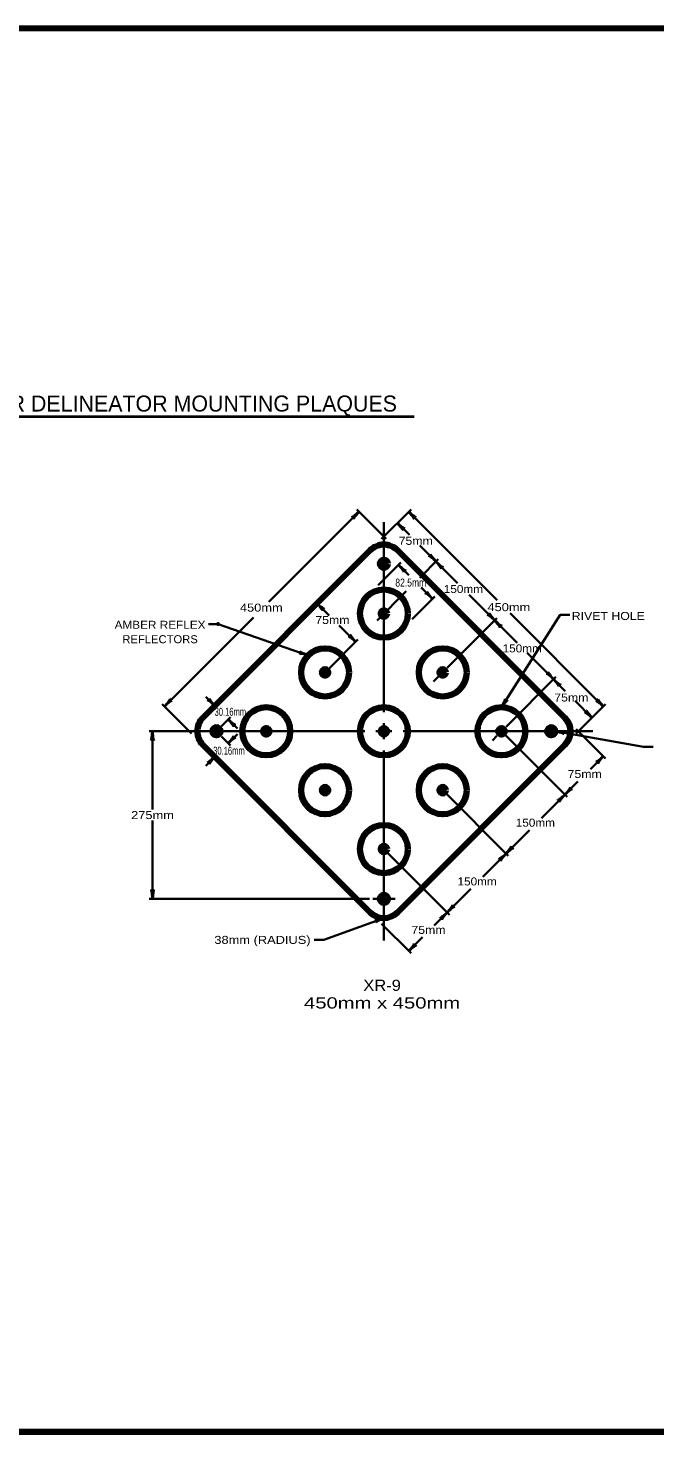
# Model space of a CAD drawing. Extents: x -74 to 639, y -412 to 42.
# Drawn here: x 181.5 to 377.5, y -402.1 to 36.3 of the extents above; entities that cross this region are included whole.
import ezdxf
from ezdxf.enums import TextEntityAlignment as Align

# ---------------------------------------------------------------- set-up
doc = ezdxf.new("R2010")
doc.units = 0
doc.header["$PDMODE"] = 32
doc.header["$PDSIZE"] = 0.5
doc.layers.add('1', color=7, linetype='Continuous', lineweight=40)

msp = doc.modelspace()

# ---------------------------------------------------------------- linework, layer by layer
at = {"layer": '1'}
msp.add_line((95.322, -84.95), (302.217, -84.95), dxfattribs=at)
at = {"layer": '1', "lineweight": 35}
for p, q in [((293.419, -123.164), (284.227, -113.972)), ((292.005, -123.164), (301.197, -113.972)), ((284.934, -114.679), (256.768, -142.845)), ((292.712, -117.942), (292.712, -177.268)), ((300.685, -121.945), (296.955, -118.215)), ((300.49, -114.679), (328.115, -142.303)), ((308.976, -130.235), (303.969, -125.228)), ((290.944, -137.66), (298.015, -130.589)), ((297.308, -131.296), (300.49, -134.478)), ((303.903, -135.308), (309.683, -129.528)), ((308.976, -130.235), (315.739, -136.999)), ((290.591, -148.62), (299.696, -139.515)), ((304.387, -138.374), (307.915, -141.902)), ((275.617, -147.082), (271.853, -143.317)), ((301.551, -148.266), (308.622, -141.195)), ((319.427, -140.687), (327.361, -148.62)), ((251.934, -147.679), (224.123, -175.49)), ((328.068, -147.913), (312.511, -163.469)), ((327.361, -148.62), (334.38, -155.64)), ((332.207, -146.395), (361.302, -175.49)), ((240.885, -149.766), (237.885, -149.766)), ((269.024, -159.58), (240.885, -149.766)), ((283.873, -155.338), (278.717, -150.182)), ((274.327, -164.884), (284.58, -154.63)), ((337.512, -158.772), (345.745, -167.005)), ((309.683, -166.297), (308.269, -167.711)), ((311.804, -164.177), (310.39, -165.591)), ((330.896, -181.854), (346.452, -166.298)), ((345.745, -167.005), (349.434, -170.694)), ((232.608, -183.975), (223.416, -174.783)), ((239.856, -175.313), (237.027, -172.485)), ((352.465, -173.725), (357.766, -179.026)), ((352.816, -183.975), (362.009, -174.783)), ((241.977, -181.677), (244.806, -178.849)), ((244.099, -179.556), (246.927, -182.384)), ((219.386, -183.268), (286.712, -183.268)), ((220.386, -183.268), (220.386, -207.719)), ((290.212, -183.268), (295.212, -183.268)), ((292.712, -180.768), (292.712, -185.768)), ((298.712, -183.268), (358.038, -183.268)), ((328.775, -183.975), (330.189, -182.561)), ((329.482, -183.268), (349.988, -203.774)), ((352.816, -182.561), (362.009, -191.754)), ((241.977, -184.859), (244.806, -187.688)), ((244.099, -186.981), (246.927, -184.152)), ((328.067, -184.683), (326.653, -186.097)), ((239.856, -191.223), (237.028, -194.052)), ((292.712, -189.268), (292.712, -248.594)), ((361.302, -191.046), (357.301, -195.047)), ((311.097, -201.653), (331.603, -222.159)), ((220.386, -211.168), (220.386, -235.594)), ((313.218, -240.544), (292.712, -220.038)), ((288.212, -235.594), (219.386, -235.594)), ((292.712, -235.594), (289.212, -235.594)), ((292.712, -235.594), (296.212, -235.594)), ((292.005, -243.372), (301.197, -252.565)), ((304.83, -247.517), (300.49, -251.858))]:
    msp.add_line(p, q, dxfattribs=at)
at = {"layer": '1', "lineweight": 90}
for p, q in [((236.144, -179.026), (288.47, -126.7)), ((296.955, -126.7), (349.281, -179.026)), ((288.47, -239.837), (236.144, -187.511)), ((349.281, -187.511), (296.955, -239.837))]:
    msp.add_line(p, q, dxfattribs=at)
at = {"layer": '1', "lineweight": 158}
msp.add_line((633.015, -402.068), (-26.651, -402.068), dxfattribs=at)
msp.add_lwpolyline([(633.015, 36.349), (-26.735, 36.265), (-26.651, -402.068)], dxfattribs=at)
at = {"layer": '1', "lineweight": 35}
for points in [[(329.482, -175.768), (347.822, -146.943), (350.822, -146.943)], [(346.288, -183.268), (373.863, -188.13), (376.863, -188.13)], [(353.363, -198.985), (349.281, -203.067), (341.942, -210.406)], [(338.202, -214.147), (330.896, -221.452), (323.626, -228.722)], [(319.928, -232.42), (312.511, -239.837), (308.463, -243.885)], [(292.712, -241.594), (273.918, -248.435), (270.918, -248.435)]]:
    msp.add_lwpolyline(points, dxfattribs=at)
at = {"layer": '1', "lineweight": 90}
for centre, radius in [((292.712, -130.942), 1.25), ((292.712, -146.499), 7.5), ((292.712, -146.499), 1), ((274.327, -164.884), 7.5), ((311.097, -164.884), 7.5), ((274.327, -164.884), 1), ((311.097, -164.884), 1), ((255.943, -183.268), 7.5), ((292.712, -183.268), 7.5), ((329.482, -183.268), 7.5), ((240.386, -183.268), 1.25), ((255.943, -183.268), 1), ((292.712, -183.268), 1), ((329.482, -183.268), 1), ((345.038, -183.268), 1.25), ((274.327, -201.653), 7.5), ((311.097, -201.653), 7.5), ((274.327, -201.653), 1), ((311.097, -201.653), 1), ((292.712, -220.038), 7.5), ((292.712, -220.038), 1), ((292.712, -235.594), 1.25)]:
    msp.add_circle(centre, radius, dxfattribs=at)
for centre, start, end in [((292.712, -130.942), 45, 135.00014), ((240.386, -183.268), 134.99979, 225), ((345.038, -183.268), 315.00029, 45), ((292.712, -235.594), 225, 314.99989)]:
    msp.add_arc(centre, 6, start, end, dxfattribs=at)
at = {"layer": '1'}
for centre, major_axis, ratio, start_param, end_param in [((283.992, -115.322), (1.366, 1.118), 0.07063, 3.1407148, 5.41811), ((283.992, -115.322), (1.366, 1.118), 0.07063, 3.1407148, 5.41811), ((284.358, -115.646), (1.152, 1.373), 0.122415, 0.8963533, 3.1415927), ((284.358, -115.646), (1.152, 1.373), 0.122415, 0.8963533, 3.1415927), ((297.598, -119.156), (-1.118, 1.366), 0.07063, 3.1407148, 5.41811), ((297.598, -119.156), (-1.118, 1.366), 0.07063, 3.1407148, 5.41811), ((297.922, -118.791), (-1.373, 1.152), 0.122415, 0.8963533, 3.1415927), ((297.922, -118.791), (-1.373, 1.152), 0.122415, 0.8963533, 3.1415927), ((301.133, -115.621), (-1.118, 1.366), 0.07063, 3.1407148, 5.41811), ((301.133, -115.621), (-1.118, 1.366), 0.07063, 3.1407148, 5.41811), ((301.457, -115.255), (-1.373, 1.152), 0.122415, 0.8963533, 3.1415927), ((301.457, -115.255), (-1.373, 1.152), 0.122415, 0.8963533, 3.1415927), ((297.951, -132.238), (-1.118, 1.366), 0.07063, 3.1407148, 5.41811), ((297.951, -132.238), (-1.118, 1.366), 0.07063, 3.1407148, 5.41811), ((298.275, -131.872), (-1.373, 1.152), 0.122415, 0.8963533, 3.1415927), ((298.275, -131.872), (-1.373, 1.152), 0.122415, 0.8963533, 3.1415927), ((308.009, -129.659), (1.373, -1.152), 0.122415, 0.8963533, 3.1415927), ((308.009, -129.659), (1.373, -1.152), 0.122415, 0.8963533, 3.1415927), ((308.333, -129.293), (1.118, -1.366), 0.07063, 3.1407148, 5.41811), ((308.333, -129.293), (1.118, -1.366), 0.07063, 3.1407148, 5.41811), ((309.618, -131.177), (-1.118, 1.366), 0.07063, 3.1407148, 5.41811), ((309.618, -131.177), (-1.118, 1.366), 0.07063, 3.1407148, 5.41811), ((309.943, -130.812), (-1.373, 1.152), 0.122415, 0.8963533, 3.1415927), ((309.943, -130.812), (-1.373, 1.152), 0.122415, 0.8963533, 3.1415927), ((306.948, -141.326), (1.373, -1.152), 0.122415, 0.8963533, 3.1415927), ((306.948, -141.326), (1.373, -1.152), 0.122415, 0.8963533, 3.1415927), ((307.272, -140.96), (1.118, -1.366), 0.07063, 3.1407148, 5.41811), ((307.272, -140.96), (1.118, -1.366), 0.07063, 3.1407148, 5.41811), ((272.495, -144.259), (-1.118, 1.366), 0.07063, 3.1407148, 5.41811), ((272.495, -144.259), (-1.118, 1.366), 0.07063, 3.1407148, 5.41811), ((272.82, -143.893), (-1.373, 1.152), 0.122415, 0.8963533, 3.1415927), ((272.82, -143.893), (-1.373, 1.152), 0.122415, 0.8963533, 3.1415927), ((326.394, -148.044), (1.373, -1.152), 0.122415, 0.8963533, 3.1415927), ((326.394, -148.044), (1.373, -1.152), 0.122415, 0.8963533, 3.1415927), ((326.718, -147.678), (1.118, -1.366), 0.07063, 3.1407148, 5.41811), ((326.718, -147.678), (1.118, -1.366), 0.07063, 3.1407148, 5.41811), ((328.003, -149.562), (-1.118, 1.366), 0.07063, 3.1407148, 5.41811), ((328.003, -149.562), (-1.118, 1.366), 0.07063, 3.1407148, 5.41811), ((328.327, -149.196), (-1.373, 1.152), 0.122415, 0.8963533, 3.1415927), ((328.327, -149.196), (-1.373, 1.152), 0.122415, 0.8963533, 3.1415927), ((283.231, -154.396), (1.118, -1.366), 0.07063, 3.1407148, 5.41811), ((283.231, -154.396), (1.118, -1.366), 0.07063, 3.1407148, 5.41811), ((282.906, -154.761), (1.373, -1.152), 0.122415, 0.8963533, 3.1415927), ((282.906, -154.761), (1.373, -1.152), 0.122415, 0.8963533, 3.1415927), ((267.903, -159.482), (1.738, -0.441), 0.122415, 0.8963533, 3.1415927), ((268.036, -159.011), (1.601, -0.744), 0.07063, 3.1407148, 5.41811), ((344.778, -166.429), (1.373, -1.152), 0.122415, 0.8963533, 3.1415927), ((344.778, -166.429), (1.373, -1.152), 0.122415, 0.8963533, 3.1415927), ((345.103, -166.063), (1.118, -1.366), 0.07063, 3.1407148, 5.41811), ((345.103, -166.063), (1.118, -1.366), 0.07063, 3.1407148, 5.41811), ((346.388, -167.947), (-1.118, 1.366), 0.07063, 3.1407148, 5.41811), ((346.388, -167.947), (-1.118, 1.366), 0.07063, 3.1407148, 5.41811), ((346.712, -167.581), (-1.373, 1.152), 0.122415, 0.8963533, 3.1415927), ((346.712, -167.581), (-1.373, 1.152), 0.122415, 0.8963533, 3.1415927), ((224.699, -174.523), (-1.152, -1.373), 0.122415, 0.8963533, 3.1415927), ((224.699, -174.523), (-1.152, -1.373), 0.122415, 0.8963533, 3.1415927), ((225.065, -174.847), (-1.366, -1.118), 0.07063, 3.1407148, 5.41811), ((225.065, -174.847), (-1.366, -1.118), 0.07063, 3.1407148, 5.41811), ((238.889, -174.737), (1.373, -1.152), 0.122415, 0.8963533, 3.1415927), ((238.889, -174.737), (1.373, -1.152), 0.122415, 0.8963533, 3.1415927), ((239.213, -174.371), (1.118, -1.366), 0.07063, 3.1407148, 5.41811), ((239.213, -174.371), (1.118, -1.366), 0.07063, 3.1407148, 5.41811), ((329.834, -174.699), (-0.827, -1.59), 0.122415, 0.8963533, 3.1415927), ((329.834, -174.699), (-0.827, -1.59), 0.122415, 0.8963533, 3.1415927), ((330.262, -174.937), (-1.091, -1.388), 0.07063, 3.1407148, 5.41811), ((330.262, -174.937), (-1.091, -1.388), 0.07063, 3.1407148, 5.41811), ((360.335, -174.914), (1.373, -1.152), 0.122415, 0.8963533, 3.1415927), ((360.335, -174.914), (1.373, -1.152), 0.122415, 0.8963533, 3.1415927), ((360.659, -174.548), (1.118, -1.366), 0.07063, 3.1407148, 5.41811), ((360.659, -174.548), (1.118, -1.366), 0.07063, 3.1407148, 5.41811), ((244.741, -180.498), (-1.118, 1.366), 0.07063, 3.1407148, 5.41811), ((244.741, -180.498), (-1.118, 1.366), 0.07063, 3.1407148, 5.41811), ((245.066, -180.132), (-1.373, 1.152), 0.122415, 0.8963533, 3.1415927), ((245.066, -180.132), (-1.373, 1.152), 0.122415, 0.8963533, 3.1415927), ((356.799, -178.45), (1.373, -1.152), 0.122415, 0.8963533, 3.1415927), ((356.799, -178.45), (1.373, -1.152), 0.122415, 0.8963533, 3.1415927), ((357.123, -178.084), (1.118, -1.366), 0.07063, 3.1407148, 5.41811), ((357.123, -178.084), (1.118, -1.366), 0.07063, 3.1407148, 5.41811), ((220.175, -184.389), (0.176, 1.756), 0.07063, 3.1407148, 5.41811), ((220.175, -184.389), (0.176, 1.756), 0.07063, 3.1407148, 5.41811), ((220.663, -184.36), (-0.156, 1.786), 0.122415, 0.8963533, 3.1415927), ((220.663, -184.36), (-0.156, 1.786), 0.122415, 0.8963533, 3.1415927), ((347.355, -183.671), (-1.699, 0.478), 0.07063, 3.1407148, 5.41811), ((347.411, -183.186), (-1.786, 0.156), 0.122415, 0.8963533, 3.1415927), ((244.675, -186.014), (-1.152, -1.373), 0.122415, 0.8963533, 3.1415927), ((244.675, -186.014), (-1.152, -1.373), 0.122415, 0.8963533, 3.1415927), ((245.041, -186.338), (-1.366, -1.118), 0.07063, 3.1407148, 5.41811), ((245.041, -186.338), (-1.366, -1.118), 0.07063, 3.1407148, 5.41811), ((238.914, -191.866), (1.366, 1.118), 0.07063, 3.1407148, 5.41811), ((238.914, -191.866), (1.366, 1.118), 0.07063, 3.1407148, 5.41811), ((239.28, -192.19), (1.152, 1.373), 0.122415, 0.8963533, 3.1415927), ((239.28, -192.19), (1.152, 1.373), 0.122415, 0.8963533, 3.1415927), ((360.36, -191.689), (1.366, 1.118), 0.07063, 3.1407148, 5.41811), ((360.36, -191.689), (1.366, 1.118), 0.07063, 3.1407148, 5.41811), ((360.725, -192.013), (1.152, 1.373), 0.122415, 0.8963533, 3.1415927), ((360.725, -192.013), (1.152, 1.373), 0.122415, 0.8963533, 3.1415927), ((349.857, -202.1), (-1.152, -1.373), 0.122415, 0.8963533, 3.1415927), ((349.857, -202.1), (-1.152, -1.373), 0.122415, 0.8963533, 3.1415927), ((350.223, -202.425), (-1.366, -1.118), 0.07063, 3.1407148, 5.41811), ((350.223, -202.425), (-1.366, -1.118), 0.07063, 3.1407148, 5.41811), ((348.339, -203.71), (1.366, 1.118), 0.07063, 3.1407148, 5.41811), ((348.339, -203.71), (1.366, 1.118), 0.07063, 3.1407148, 5.41811), ((348.705, -204.034), (1.152, 1.373), 0.122415, 0.8963533, 3.1415927), ((348.705, -204.034), (1.152, 1.373), 0.122415, 0.8963533, 3.1415927), ((331.472, -220.485), (-1.152, -1.373), 0.122415, 0.8963533, 3.1415927), ((331.472, -220.485), (-1.152, -1.373), 0.122415, 0.8963533, 3.1415927), ((329.954, -222.095), (1.366, 1.118), 0.07063, 3.1407148, 5.41811), ((329.954, -222.095), (1.366, 1.118), 0.07063, 3.1407148, 5.41811), ((330.32, -222.419), (1.152, 1.373), 0.122415, 0.8963533, 3.1415927), ((330.32, -222.419), (1.152, 1.373), 0.122415, 0.8963533, 3.1415927), ((331.838, -220.809), (-1.366, -1.118), 0.07063, 3.1407148, 5.41811), ((331.838, -220.809), (-1.366, -1.118), 0.07063, 3.1407148, 5.41811), ((220.11, -234.503), (0.156, -1.786), 0.122415, 0.8963533, 3.1415927), ((220.11, -234.503), (0.156, -1.786), 0.122415, 0.8963533, 3.1415927), ((220.598, -234.474), (-0.176, -1.756), 0.07063, 3.1407148, 5.41811), ((220.598, -234.474), (-0.176, -1.756), 0.07063, 3.1407148, 5.41811), ((311.569, -240.48), (1.366, 1.118), 0.07063, 3.1407148, 5.41811), ((311.569, -240.48), (1.366, 1.118), 0.07063, 3.1407148, 5.41811), ((311.935, -240.804), (1.152, 1.373), 0.122415, 0.8963533, 3.1415927), ((311.935, -240.804), (1.152, 1.373), 0.122415, 0.8963533, 3.1415927), ((313.087, -238.87), (-1.152, -1.373), 0.122415, 0.8963533, 3.1415927), ((313.087, -238.87), (-1.152, -1.373), 0.122415, 0.8963533, 3.1415927), ((313.453, -239.194), (-1.366, -1.118), 0.07063, 3.1407148, 5.41811), ((313.453, -239.194), (-1.366, -1.118), 0.07063, 3.1407148, 5.41811), ((291.587, -241.779), (1.711, 0.436), 0.07063, 3.1407148, 5.41811), ((291.781, -242.227), (1.625, 0.757), 0.122415, 0.8963533, 3.1415927), ((301.067, -250.891), (-1.152, -1.373), 0.122415, 0.8963533, 3.1415927), ((301.432, -251.215), (-1.366, -1.118), 0.07063, 3.1407148, 5.41811)]:
    msp.add_ellipse(centre, major_axis=major_axis, ratio=ratio, start_param=start_param, end_param=end_param, dxfattribs=at)
msp.add_point((240.885, -149.766), dxfattribs=at)

# ---------------------------------------------------------------- texts
msp.add_text('PUNCHING DETAILS FOR DELINEATOR MOUNTING PLAQUES', height=5, dxfattribs=at).set_placement((197.989, -83.404), align=Align.CENTER)
msp.add_text('PUNCHING DETAILS FOR DELINEATOR MOUNTING PLAQUES', height=5, dxfattribs=at).set_placement((197.989, -83.404), align=Align.CENTER)
for s, height, width, p in [('75mm', 2.5, 1.15, (302.669, -125.031)), ('82.5mm', 2.5, 0.8, (301.12, -138.071)), ('150mm', 2.5, 1.1, (317.576, -140.086)), ('450mm', 2.5, 1.2, (254.399, -145.891)), ('450mm', 2.5, 1.2, (331.784, -145.743)), ('AMBER REFLEX', 2.5, 1.1, (222.745, -151.259)), ('75mm', 2.5, 1.15, (276.628, -149.747)), ('RIVET HOLE', 2.5, 1.15, (362.874, -148.496)), ('REFLECTORS', 2.5, 1.05, (222.745, -155.759)), ('150mm', 2.5, 1.1, (335.961, -158.619)), ('75mm', 2.5, 1.15, (351.312, -173.969)), ('30.16mm', 2.5, 0.65, (244.727, -178.43)), ('30.16mm', 2.5, 0.65, (244.283, -190.566)), ('75mm', 2.5, 1.15, (355.492, -197.847)), ('275mm', 2.5, 1.2, (220.386, -210.681)), ('150mm', 2.5, 1.1, (340.067, -213.05)), ('150mm', 2.5, 1.1, (321.867, -231.401)), ('75mm', 2.5, 1.15, (306.664, -246.539)), ('38mm (RADIUS)', 2.5, 1.2, (254.764, -249.659)), ('XR-9', 3.5, 1.1, (292.155, -264.337)), ('450mm x 450mm', 3.5, 1.35, (292.155, -269.837))]:
    msp.add_text(s, height=height, dxfattribs=dict(at, width=width)).set_placement(p, align=Align.CENTER)

doc.saveas('drawing.dxf')
